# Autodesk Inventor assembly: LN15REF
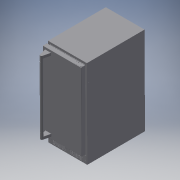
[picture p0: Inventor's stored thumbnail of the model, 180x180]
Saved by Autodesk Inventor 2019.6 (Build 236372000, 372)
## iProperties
Company: none
Created: 2025-04
Part Number: LN15REF
Description: CATIA V5 STEP
Document SubType Name: Assembly
Designer: MMAK
Authority: none
Title: C:\Users\MMAK\Documents\SmarTeam\WEBSITE CAD\Lynx STP\LN15REF.stp
Author: none
Sending System: CATIA V5 STEP AP203 v2
Preprocessor: CATIA Unofficial Packaging Version SP2
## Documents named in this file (4)
- C:\Users\MMAK\Documents\SmarTeam\WEBSITE CAD\Lynx STP\LN15REF.iam
- C:\Users\MMAK\Documents\SmarTeam\WEBSITE CAD\Lynx STP\LOCL215-SS01A.iam
- C:\Users\MMAK\Documents\SmarTeam\WEBSITE CAD\Lynx STP\OC UC 15.ipt
- C:\Users\MMAK\Documents\SmarTeam\WEBSITE CAD\Lynx STP\Product90.iam
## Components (3 placed, 3 different names)
1. LOCL215-SS01A.1 [sub-assembly]
2. OC UC 15.1
3. Product90.1 [sub-assembly]
